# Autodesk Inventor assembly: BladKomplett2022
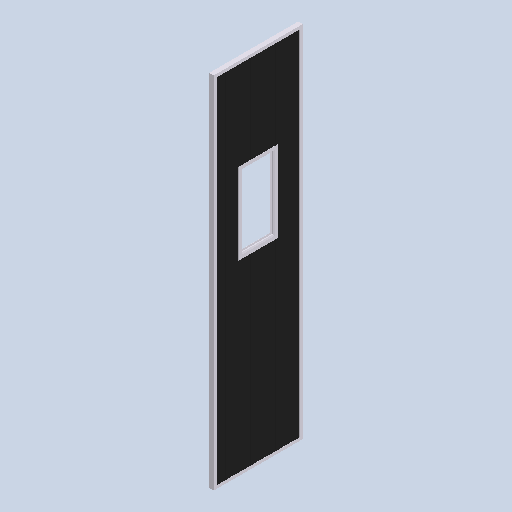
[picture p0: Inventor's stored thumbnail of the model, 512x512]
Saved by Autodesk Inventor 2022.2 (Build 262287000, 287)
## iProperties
Created: 2022-02
Part Number: BladKomplett2022
Document SubType Name: Assembly
Designer: cl
Author: cl
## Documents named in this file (5)
- G:\AutoCad\Carl Lund\3D-modeller systemlösningar\3D-modell-systemlösning-2022\Parts\BladKomplett2022.iam
- G:\AutoCad\Carl Lund\3D-modeller systemlösningar\3D-modell-systemlösning-2022\Parts\Blad.ipt
- G:\AutoCad\Carl Lund\3D-modeller systemlösningar\3D-modell-systemlösning-2022\Parts\AluKarmBlad.ipt
- G:\AutoCad\Carl Lund\3D-modeller systemlösningar\3D-modell-systemlösning-2022\Parts\Fönsterkarm.ipt
- G:\AutoCad\Carl Lund\3D-modeller systemlösningar\3D-modell-systemlösning-2022\Styrande.iam
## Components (4 placed, 3 different names)
1. Blad:1 — Mate:1, Mate:2, Flush:1, Mate:3, Flush:2, Flush:3, Mate:4
2. AluKarmBlad:1 — Mate:3, Flush:2, Flush:3, Flush:4, Flush:8
3. Fönsterkarm:1 — Mate:4, Flush:4, Flush:5, Flush:6, Flush:7, Flush:8
4. Fönsterkarm:2 — Flush:5, Flush:6, Flush:7
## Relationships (12: Flush 8, Mate 4)
- Mate:1: Blad:1
- Mate:2: Blad:1
- Flush:1: Blad:1
- Mate:3: Blad:1 ↔ AluKarmBlad:1
- Flush:2: Blad:1 ↔ AluKarmBlad:1
- Flush:3: Blad:1 ↔ AluKarmBlad:1
- Mate:4: Blad:1 ↔ Fönsterkarm:1
- Flush:4: AluKarmBlad:1 ↔ Fönsterkarm:1
- Flush:5: Fönsterkarm:1 ↔ Fönsterkarm:2
- Flush:6: Fönsterkarm:1 ↔ Fönsterkarm:2
- Flush:7: Fönsterkarm:1 ↔ Fönsterkarm:2
- Flush:8: AluKarmBlad:1 ↔ Fönsterkarm:1
## Named parameters: BladBredd = 987.5 mm, Fönsterhöjd = 862 mm, Blad2 = 1012.5 mm, Blad3 = 0, Blad4 = 0, Blad5 = 1012.5 mm, Blad6 = 2025 mm, MGJ12Djup = 0, MGJ12Bredd = 0, MGJ2Djup = 0, MGJ2Bredd = 5012.5 mm, MGJ56Djup = 0, MGJ56Bredd = 0, MGJ23Djup = 48 mm, MGJ45Djup = 48 mm, GarageRegel5 = 0, GarageRegel6 = 0, Styrrulle2Djup = 0, FönsterhöjdStyrning = 862 mm, FönsterKarm = 54 mm, AndraGlasraden = 0, BrösthöjdStyrning2 = 0.0001 mm
